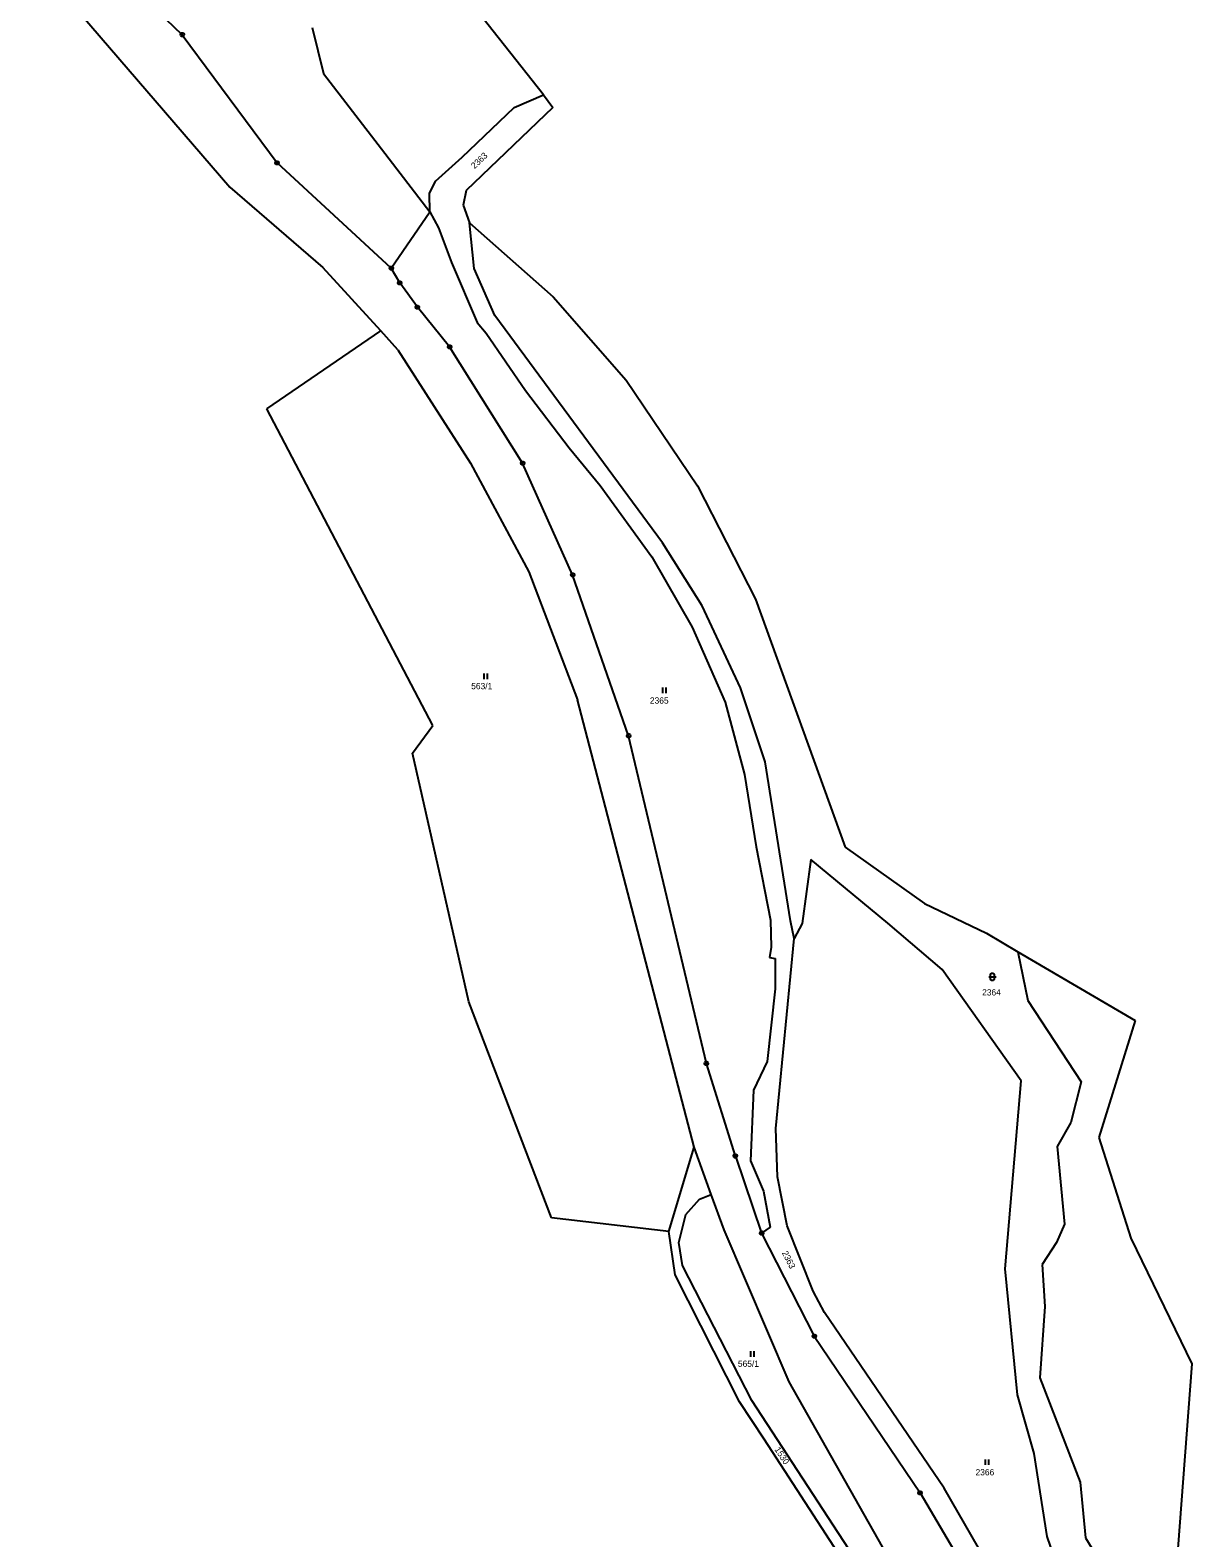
# Model space of a CAD drawing. Extents: x -852001 to -848657, y -1054973 to -1052182.
# Drawn here: x -849116 to -848802.3, y -1053436.2 to -1053029 of the extents above; entities that cross this region are included whole.
import ezdxf

# ---------------------------------------------------------------- set-up
doc = ezdxf.new("R2010")
doc.units = 0
for name, color, linetype in [('KN_HRANICE', 7, 'Continuous'), ('KN_KULTURY', 7, 'Continuous'), ('KN_MEZNIKY', 7, 'Continuous'), ('KN_PARCELY', 7, 'Continuous')]:
    doc.layers.add(name, color=color, linetype=linetype)

# ---------------------------------------------------------------- blocks, each defined once
blk = doc.blocks.new('306')
for p, q in [((-0.5, 1.5), (-0.5, 0)), ((0.5, 0), (0.5, 1.5))]:
    blk.add_line(p, q)
blk = doc.blocks.new('316')
for points in [[(-1, 1), (0.27, 1), (1, 1)], [(-0.5, 1.5), (-0.4, 1.79), (-0.15, 1.97), (0.16, 1.97), (0.41, 1.79), (0.51, 1.5), (0.51, 0.5), (0.41, 0.21), (0.16, 0.03), (-0.15, 0.03), (-0.4, 0.21), (-0.5, 0.5), (-0.5, 1.5)]]:
    blk.add_lwpolyline(points)
blk = doc.blocks.new('105')
blk.add_line((-0.12, 0), (0.12, 0))
blk.add_lwpolyline([(0.15, 0.48), (0.4, 0.3), (0.5, 0.01), (0.4, -0.28), (0.15, -0.46), (-0.16, -0.46), (-0.41, -0.28), (-0.51, 0.01), (-0.41, 0.3), (-0.16, 0.48), (0.15, 0.48)])

msp = doc.modelspace()

# ---------------------------------------------------------------- linework, layer by layer
at = {"layer": 'KN_HRANICE'}
for p, q in [((-849074.9, -1053030.24), (-849115.97, -1052991.03)), ((-848977.37, -1053046.46), (-848999.77, -1053018.11)), ((-849104.61, -1053022.02), (-849062.09, -1053071.39)), ((-849074.9, -1053030.24), (-849049.32, -1053064.85)), ((-849039.79, -1053028.27), (-849036.74, -1053040.73)), ((-849036.74, -1053040.73), (-849021.08, -1053061.03)), ((-848985.3, -1053049.9), (-848977.37, -1053046.46)), ((-848977.37, -1053046.46), (-848974.87, -1053049.93)), ((-848999.37, -1053063.31), (-848985.3, -1053049.9)), ((-848974.87, -1053049.93), (-848998.27, -1053072.31)), ((-849021.08, -1053061.03), (-849008.1, -1053078.06)), ((-849018.49, -1053093.32), (-849049.32, -1053064.85)), ((-849006.55, -1053069.76), (-848999.37, -1053063.31)), ((-849008.15, -1053073.17), (-849006.55, -1053069.76)), ((-849062.09, -1053071.39), (-849036.95, -1053093.15)), ((-849008.1, -1053078.06), (-849008.15, -1053073.17)), ((-848998.27, -1053072.31), (-848999.09, -1053076.28)), ((-849018.49, -1053093.32), (-849008.1, -1053078.06)), ((-849008.1, -1053078.06), (-849005.74, -1053082.37)), ((-848999.09, -1053076.28), (-848997.36, -1053081.01)), ((-849005.74, -1053082.37), (-849002.21, -1053091.72)), ((-848997.36, -1053081.01), (-848974.77, -1053101.03)), ((-848996.12, -1053093.41), (-848997.36, -1053081.01)), ((-849021.3, -1053110.24), (-849036.95, -1053093.15)), ((-849016.18, -1053097.26), (-849018.49, -1053093.32)), ((-849002.21, -1053091.72), (-848995.27, -1053107.95)), ((-848990.47, -1053106.07), (-848996.12, -1053093.41)), ((-849011.4, -1053103.81), (-849016.18, -1053097.26)), ((-848974.77, -1053101.03), (-848955.02, -1053123.55)), ((-849002.73, -1053114.54), (-849011.4, -1053103.81)), ((-848945.27, -1053167.48), (-848990.47, -1053106.07)), ((-849052.04, -1053131.25), (-849021.3, -1053110.24)), ((-849016.66, -1053115.31), (-849021.3, -1053110.24)), ((-848995.27, -1053107.95), (-848992.86, -1053110.85)), ((-848992.86, -1053110.85), (-848982.27, -1053126.29)), ((-849016.66, -1053115.31), (-848997.09, -1053145.93)), ((-848983, -1053145.94), (-849002.73, -1053114.54)), ((-848955.02, -1053123.55), (-848935.76, -1053152.04)), ((-848982.27, -1053126.29), (-848970.41, -1053141.8)), ((-849007.23, -1053216.8), (-849052.04, -1053131.25)), ((-848970.41, -1053141.8), (-848962.07, -1053152.01)), ((-848997.09, -1053145.93), (-848981.37, -1053175.26)), ((-848969.53, -1053176.1), (-848983, -1053145.94)), ((-848962.07, -1053152.01), (-848948.1, -1053171.29)), ((-848935.76, -1053152.04), (-848920.11, -1053182.65)), ((-848934.55, -1053184.48), (-848945.27, -1053167.48)), ((-848948.1, -1053171.29), (-848937.28, -1053190.28)), ((-848981.37, -1053175.26), (-848968.2, -1053209.85)), ((-848954.4, -1053219.56), (-848969.53, -1053176.1)), ((-848924.23, -1053206.61), (-848934.55, -1053184.48)), ((-848920.11, -1053182.65), (-848895.91, -1053249.67)), ((-848937.28, -1053190.28), (-848928.31, -1053210.47)), ((-848917.5, -1053226.61), (-848924.23, -1053206.61)), ((-848936.74, -1053330.64), (-848968.2, -1053209.85)), ((-848928.31, -1053210.47), (-848923.13, -1053230.03)), ((-849012.75, -1053224.27), (-849007.23, -1053216.8)), ((-848933.4, -1053308.05), (-848954.4, -1053219.56)), ((-848997.5, -1053291.4), (-849012.75, -1053224.27)), ((-848910.7, -1053269.52), (-848917.5, -1053226.61)), ((-848923.13, -1053230.03), (-848919.96, -1053249.53)), ((-848919.96, -1053249.53), (-848916.06, -1053269.39)), ((-848895.91, -1053249.67), (-848874.52, -1053264.9)), ((-848905.2, -1053253.03), (-848907.5, -1053270.25)), ((-848884.39, -1053270.14), (-848905.2, -1053253.03)), ((-848874.52, -1053264.9), (-848857.79, -1053272.92)), ((-848916.06, -1053269.39), (-848915.91, -1053276.62)), ((-848909.7, -1053274.35), (-848910.7, -1053269.52)), ((-848907.5, -1053270.25), (-848909.7, -1053274.35)), ((-848869.78, -1053282.72), (-848884.39, -1053270.14)), ((-848914.62, -1053325.59), (-848909.7, -1053274.35)), ((-848857.79, -1053272.92), (-848849.27, -1053277.91)), ((-848915.91, -1053276.62), (-848916.33, -1053279.44)), ((-848849.27, -1053277.91), (-848817.6, -1053296.47)), ((-848849.27, -1053277.91), (-848846.59, -1053291.04)), ((-848916.33, -1053279.44), (-848914.83, -1053279.68)), ((-848914.83, -1053279.68), (-848914.85, -1053287.87)), ((-848848.43, -1053312.77), (-848869.78, -1053282.72)), ((-848914.85, -1053287.87), (-848916.95, -1053307.56)), ((-848846.59, -1053291.04), (-848832.25, -1053313.05)), ((-848975.18, -1053349.78), (-848997.5, -1053291.4)), ((-848817.6, -1053296.47), (-848827.42, -1053328.03)), ((-848925.57, -1053333.06), (-848933.4, -1053308.05)), ((-848916.95, -1053307.56), (-848920.71, -1053315.28)), ((-848920.71, -1053315.28), (-848921.52, -1053334.36)), ((-848852.74, -1053363.51), (-848848.43, -1053312.77)), ((-848832.25, -1053313.05), (-848834.97, -1053323.98)), ((-848914.18, -1053338.69), (-848914.62, -1053325.59)), ((-848834.97, -1053323.98), (-848838.73, -1053330.45)), ((-848943.5, -1053353.45), (-848936.74, -1053330.64)), ((-848932.07, -1053343.45), (-848936.74, -1053330.64)), ((-848838.73, -1053330.45), (-848836.7, -1053351.46)), ((-848827.42, -1053328.03), (-848818.78, -1053355.27)), ((-848925.57, -1053333.06), (-848918.5, -1053353.87)), ((-848921.52, -1053334.36), (-848917.99, -1053342.58)), ((-848911.62, -1053351.88), (-848914.18, -1053338.69)), ((-848935.27, -1053344.69), (-848932.07, -1053343.45)), ((-848928.59, -1053353), (-848932.07, -1053343.45)), ((-848917.99, -1053342.58), (-848916.16, -1053352.31)), ((-848938.98, -1053348.88), (-848935.27, -1053344.69)), ((-848943.5, -1053353.45), (-848975.18, -1053349.78)), ((-848940.85, -1053356.42), (-848938.98, -1053348.88)), ((-848904.56, -1053369.55), (-848911.62, -1053351.88)), ((-848836.7, -1053351.46), (-848838.9, -1053356.41)), ((-848941.85, -1053365.12), (-848943.5, -1053353.45)), ((-848911.04, -1053394.01), (-848928.59, -1053353)), ((-848916.16, -1053352.31), (-848918.5, -1053353.87)), ((-848918.5, -1053353.87), (-848904.29, -1053381.74)), ((-848818.78, -1053355.27), (-848802.33, -1053389.15)), ((-848939.85, -1053362.61), (-848940.85, -1053356.42)), ((-848838.9, -1053356.41), (-848842.7, -1053362.4)), ((-848921.13, -1053399.1), (-848939.85, -1053362.61)), ((-848849.36, -1053397.56), (-848852.74, -1053363.51)), ((-848842.7, -1053362.4), (-848842.06, -1053373.66)), ((-848924.42, -1053399.45), (-848941.85, -1053365.12)), ((-848901.49, -1053375.29), (-848904.56, -1053369.55)), ((-848869.21, -1053422.76), (-848901.49, -1053375.29)), ((-848842.06, -1053373.66), (-848843.36, -1053392.98)), ((-848904.29, -1053381.74), (-848875.72, -1053424.05)), ((-848802.33, -1053389.15), (-848806.13, -1053439.07)), ((-848857.83, -1053488.12), (-848911.04, -1053394.01)), ((-848843.36, -1053392.98), (-848832.47, -1053421.12)), ((-848917.77, -1053409.54), (-848924.42, -1053399.45)), ((-848893.56, -1053441.34), (-848921.13, -1053399.1)), ((-848844.92, -1053413.4), (-848849.36, -1053397.56)), ((-848888.8, -1053454.15), (-848917.77, -1053409.54)), ((-848841.43, -1053435.85), (-848844.92, -1053413.4)), ((-848832.47, -1053421.12), (-848831.07, -1053436.17)), ((-848875.72, -1053424.05), (-848862.99, -1053445.49)), ((-848855.28, -1053446.92), (-848869.21, -1053422.76)), ((-848837.43, -1053447.3), (-848841.43, -1053435.85)), ((-848831.07, -1053436.17), (-848811.13, -1053468.66))]:
    msp.add_line(p, q, dxfattribs=at)

# ---------------------------------------------------------------- block references
at = {"layer": 'KN_KULTURY'}
for name, p in [('306', (-848993, -1053204.3)), ('306', (-848944.72, -1053208.03)), ('316', (-848856.17, -1053285.67)), ('306', (-848921, -1053387.3)), ('306', (-848857.63, -1053416.48))]:
    msp.add_blockref(name, p, dxfattribs=at)
at = {"layer": 'KN_MEZNIKY'}
for p in [(-849074.9, -1053030.24), (-849049.32, -1053064.85), (-849018.49, -1053093.32), (-849016.18, -1053097.26), (-849011.4, -1053103.81), (-849002.73, -1053114.54), (-848983, -1053145.94), (-848969.53, -1053176.1), (-848954.4, -1053219.56), (-848933.4, -1053308.05), (-848925.57, -1053333.06), (-848918.5, -1053353.87), (-848904.29, -1053381.74), (-848875.72, -1053424.05)]:
    msp.add_blockref('105', p, dxfattribs=at)

# ---------------------------------------------------------------- texts
at = {"layer": 'KN_PARCELY'}
for s, rotation, p in [('2363', 43.831, (-848995.97, -1053066.58)), ('2363', 297.021, (-848913.07, -1053359.2)), ('1530', 303.496, (-848915.09, -1053412.33))]:
    msp.add_text(s, height=1.7, rotation=rotation, dxfattribs=at).set_placement(p)
for s, p in [('563/1', (-848996.89, -1053207)), ('2365', (-848948.65, -1053210.9)), ('2364', (-848858.95, -1053289.71)), ('565/1', (-848924.89, -1053390)), ('2366', (-848860.73, -1053419.31))]:
    msp.add_text(s, height=1.7, dxfattribs=at).set_placement(p)

doc.saveas('drawing.dxf')
